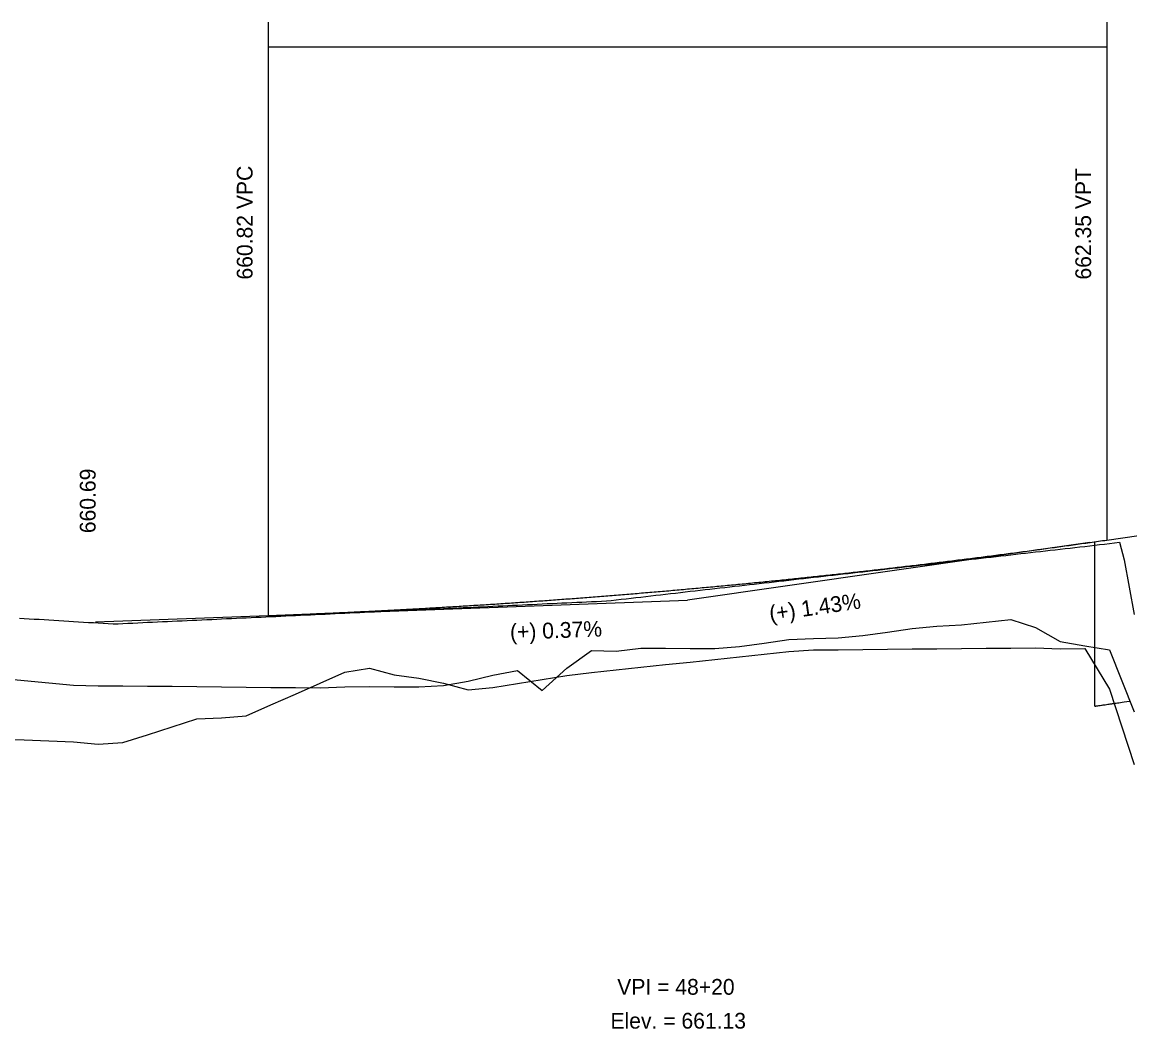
# Model space of a CAD drawing. Extents: x 1733584 to 1737559, y 1214897 to 1219897.
# Drawn here: x 1735164.9 to 1735389.4, y 1217921.2 to 1218125.3 of the extents above; entities that cross this region are included whole.
import ezdxf

# ---------------------------------------------------------------- set-up
doc = ezdxf.new("R2010")
doc.units = 0
for name, color, linetype in [('RD_DDB_GradeTX', 7, 'Continuous'), ('RD_DDB_Profile_EX', 7, 'Continuous'), ('RD_DDB_Profile_Lbl', 7, 'Continuous'), ('RD_DDB_Profile_PR', 7, 'Continuous'), ('RD_DDB_StripGrade', 7, 'Continuous'), ('RD_DDB_VCLbl', 7, 'Continuous'), ('RD_PD_Bridge', 7, 'Continuous'), ('RD_Sketch1', 7, 'Continuous'), ('RD_Sketch2', 7, 'Continuous')]:
    doc.layers.add(name, color=color, linetype=linetype)

msp = doc.modelspace()

# ---------------------------------------------------------------- linework, layer by layer
at = {"layer": 'RD_DDB_GradeTX'}
for p in [(1735381.34, 1218019.81), (1735217.43, 1218005.08)]:
    msp.add_line(p, (1735299.77, 1218008.11), dxfattribs=at)
at = {"layer": 'RD_DDB_Profile_EX'}
for points in [[(1735280.31, 1218007.82), (1735281.31, 1218007.86), (1735282.31, 1218007.91), (1735283.31, 1218007.96), (1735284.31, 1218008.07), (1735285.31, 1218008.18), (1735286.31, 1218008.29), (1735287.31, 1218008.41), (1735288.31, 1218008.52), (1735289.31, 1218008.64), (1735290.31, 1218008.75), (1735291.31, 1218008.87), (1735292.31, 1218008.98), (1735293.31, 1218009.1), (1735294.31, 1218009.21), (1735295.31, 1218009.33), (1735296.31, 1218009.44), (1735297.31, 1218009.55), (1735298.31, 1218009.67), (1735299.31, 1218009.78), (1735300.31, 1218009.9), (1735301.31, 1218010.01), (1735302.31, 1218010.13), (1735303.31, 1218010.24), (1735304.31, 1218010.36), (1735305.31, 1218010.47), (1735306.31, 1218010.58), (1735307.31, 1218010.7), (1735308.31, 1218010.81), (1735309.31, 1218010.92), (1735310.31, 1218011.04), (1735311.31, 1218011.15), (1735312.31, 1218011.26), (1735313.31, 1218011.38), (1735314.31, 1218011.49), (1735315.31, 1218011.6), (1735316.31, 1218011.72), (1735317.31, 1218011.83), (1735318.31, 1218011.95), (1735319.31, 1218012.06), (1735320.31, 1218012.17), (1735321.31, 1218012.29), (1735322.31, 1218012.4), (1735323.31, 1218012.51), (1735324.31, 1218012.63), (1735325.31, 1218012.74), (1735326.31, 1218012.85), (1735327.31, 1218012.97), (1735328.31, 1218013.08), (1735329.31, 1218013.19), (1735330.31, 1218013.31), (1735331.31, 1218013.42), (1735332.31, 1218013.54), (1735333.31, 1218013.65), (1735334.31, 1218013.77), (1735335.31, 1218013.88), (1735336.31, 1218014), (1735337.31, 1218014.11), (1735338.31, 1218014.22), (1735339.31, 1218014.34), (1735340.31, 1218014.45), (1735341.31, 1218014.57), (1735342.31, 1218014.68), (1735343.31, 1218014.79), (1735344.31, 1218014.91), (1735345.31, 1218015.02), (1735346.31, 1218015.13), (1735347.31, 1218015.25), (1735348.31, 1218015.36), (1735349.31, 1218015.48), (1735350.31, 1218015.59), (1735351.31, 1218015.7), (1735352.31, 1218015.82), (1735353.31, 1218015.93), (1735354.31, 1218016.04), (1735355.31, 1218016.16), (1735356.31, 1218016.27), (1735357.31, 1218016.39), (1735358.31, 1218016.51), (1735359.31, 1218016.62), (1735360.31, 1218016.74), (1735361.31, 1218016.85), (1735362.31, 1218016.97), (1735363.31, 1218017.08), (1735364.31, 1218017.19), (1735365.31, 1218017.31), (1735366.31, 1218017.42), (1735367.31, 1218017.54), (1735368.31, 1218017.65), (1735369.31, 1218017.76), (1735370.31, 1218017.88), (1735371.31, 1218017.99), (1735372.31, 1218018.11), (1735373.31, 1218018.22), (1735374.31, 1218018.33), (1735375.31, 1218018.45), (1735376.31, 1218018.56), (1735377.31, 1218018.68), (1735378.31, 1218018.79), (1735379.31, 1218018.9), (1735380.31, 1218019.02)], [(1735380.31, 1218019.02), (1735381.31, 1218019.13), (1735382.31, 1218019.25), (1735383.31, 1218019.38), (1735384.31, 1218019.49), (1735385.31, 1218019.61), (1735386.31, 1218019.72), (1735387.31, 1218019.84), (1735388.31, 1218016.3), (1735389.31, 1218010.76), (1735390.31, 1218005.23)], [(1735180.31, 1218003.49), (1735181.31, 1218003.43), (1735182.31, 1218003.37), (1735183.31, 1218003.3), (1735184.31, 1218003.33), (1735185.31, 1218003.38), (1735186.31, 1218003.43), (1735187.31, 1218003.47), (1735188.31, 1218003.52), (1735189.31, 1218003.57), (1735190.31, 1218003.62), (1735191.31, 1218003.66), (1735192.31, 1218003.71), (1735193.31, 1218003.76), (1735194.31, 1218003.8), (1735195.31, 1218003.85), (1735196.31, 1218003.9), (1735197.31, 1218003.94), (1735198.31, 1218003.99), (1735199.31, 1218004.04), (1735200.31, 1218004.08), (1735201.31, 1218004.13), (1735202.31, 1218004.18), (1735203.31, 1218004.22), (1735204.31, 1218004.27), (1735205.31, 1218004.32), (1735206.31, 1218004.36), (1735207.31, 1218004.41), (1735208.31, 1218004.46), (1735209.31, 1218004.5), (1735210.31, 1218004.55), (1735211.31, 1218004.6), (1735212.31, 1218004.64), (1735213.31, 1218004.69), (1735214.31, 1218004.74), (1735215.31, 1218004.78), (1735216.31, 1218004.83), (1735217.31, 1218004.88), (1735218.31, 1218004.92), (1735219.31, 1218004.97), (1735220.31, 1218005.02), (1735221.31, 1218005.06), (1735222.31, 1218005.11), (1735223.31, 1218005.16), (1735224.31, 1218005.2), (1735225.31, 1218005.25), (1735226.31, 1218005.3), (1735227.31, 1218005.34), (1735228.31, 1218005.39), (1735229.31, 1218005.44), (1735230.31, 1218005.48), (1735231.31, 1218005.53), (1735232.31, 1218005.58), (1735233.31, 1218005.62), (1735234.31, 1218005.67), (1735235.31, 1218005.72), (1735236.31, 1218005.76), (1735237.31, 1218005.81), (1735238.31, 1218005.86), (1735239.31, 1218005.9), (1735240.31, 1218005.95), (1735241.31, 1218006), (1735242.31, 1218006.04), (1735243.31, 1218006.09), (1735244.31, 1218006.14), (1735245.31, 1218006.18), (1735246.31, 1218006.23), (1735247.31, 1218006.28), (1735248.31, 1218006.32), (1735249.31, 1218006.37), (1735250.31, 1218006.42), (1735251.31, 1218006.46), (1735252.31, 1218006.51), (1735253.31, 1218006.56), (1735254.31, 1218006.6), (1735255.31, 1218006.65), (1735256.31, 1218006.7), (1735257.31, 1218006.74), (1735258.31, 1218006.79), (1735259.31, 1218006.84), (1735260.31, 1218006.88), (1735261.31, 1218006.93), (1735262.31, 1218006.98), (1735263.31, 1218007.02), (1735264.31, 1218007.07), (1735265.31, 1218007.12), (1735266.31, 1218007.16), (1735267.31, 1218007.21), (1735268.31, 1218007.26), (1735269.31, 1218007.3), (1735270.31, 1218007.35), (1735271.31, 1218007.4), (1735272.31, 1218007.44), (1735273.31, 1218007.49), (1735274.31, 1218007.54), (1735275.31, 1218007.58), (1735276.31, 1218007.63), (1735277.31, 1218007.68), (1735278.31, 1218007.72), (1735279.31, 1218007.77), (1735280.31, 1218007.82)], [(1735164.31, 1218004.47), (1735165.31, 1218004.41), (1735166.31, 1218004.35), (1735167.31, 1218004.29), (1735168.31, 1218004.23), (1735169.31, 1218004.17), (1735170.31, 1218004.11), (1735171.31, 1218004.04), (1735172.31, 1218003.98), (1735173.31, 1218003.92), (1735174.31, 1218003.86), (1735175.31, 1218003.8), (1735176.31, 1218003.74), (1735177.31, 1218003.67), (1735178.31, 1218003.61), (1735179.31, 1218003.55), (1735180.31, 1218003.49)]]:
    msp.add_lwpolyline(points, dxfattribs=at)
at = {"layer": 'RD_DDB_Profile_PR'}
for p, q in [((1735384.77, 1218020.3), (1735504.77, 1218037.5)), ((1735179.77, 1218003.69), (1735214.77, 1218004.98))]:
    msp.add_line(p, q, dxfattribs=at)
msp.add_spline([(1735214.77, 1218004.98), (1735218.17, 1218005.11), (1735221.57, 1218005.25), (1735224.97, 1218005.39), (1735228.37, 1218005.54), (1735231.77, 1218005.7), (1735235.17, 1218005.86), (1735238.57, 1218006.04), (1735241.97, 1218006.22), (1735245.37, 1218006.4), (1735248.77, 1218006.6), (1735252.17, 1218006.8), (1735255.57, 1218007.01), (1735258.97, 1218007.22), (1735262.37, 1218007.44), (1735265.77, 1218007.67), (1735269.17, 1218007.91), (1735272.57, 1218008.16), (1735275.97, 1218008.41), (1735279.37, 1218008.67), (1735282.77, 1218008.93), (1735286.17, 1218009.21), (1735289.57, 1218009.49), (1735292.97, 1218009.78), (1735296.37, 1218010.07), (1735299.77, 1218010.38), (1735303.17, 1218010.69), (1735306.57, 1218011), (1735309.97, 1218011.33), (1735313.37, 1218011.66), (1735316.77, 1218012), (1735320.17, 1218012.34), (1735323.57, 1218012.7), (1735326.97, 1218013.06), (1735330.37, 1218013.43), (1735333.77, 1218013.8), (1735337.17, 1218014.18), (1735340.57, 1218014.57), (1735343.97, 1218014.97), (1735347.37, 1218015.37), (1735350.77, 1218015.79), (1735354.17, 1218016.2), (1735357.57, 1218016.63), (1735360.97, 1218017.06), (1735364.37, 1218017.5), (1735367.77, 1218017.95), (1735371.17, 1218018.41), (1735374.57, 1218018.87), (1735377.97, 1218019.34), (1735381.37, 1218019.81), (1735384.77, 1218020.3)], degree=3, dxfattribs=at)
at = {"layer": 'RD_DDB_VCLbl'}
for p, q in [((1735214.77, 1218125.3), (1735214.77, 1218004.98)), ((1735384.77, 1218125.3), (1735384.77, 1218020.3)), ((1735214.77, 1218120.3), (1735384.77, 1218120.3))]:
    msp.add_line(p, q, dxfattribs=at)
at = {"layer": 'RD_PD_Bridge'}
msp.add_line((1735382.32, 1217986.63), (1735382.32, 1218019.95), dxfattribs=at)
msp.add_open_spline([(1735382.32, 1217986.63), (1735382.34, 1217986.63), (1735382.39, 1217986.63), (1735382.45, 1217986.64), (1735382.49, 1217986.65), (1735382.51, 1217986.65), (1735382.52, 1217986.65), (1735382.53, 1217986.65), (1735382.6, 1217986.66), (1735382.66, 1217986.67), (1735383.16, 1217986.74), (1735383.6, 1217986.8), (1735384.51, 1217986.93), (1735384.96, 1217986.99), (1735385.54, 1217987.08), (1735385.72, 1217987.1), (1735385.91, 1217987.13), (1735385.99, 1217987.14), (1735386.01, 1217987.14), (1735386.02, 1217987.14), (1735386.02, 1217987.14), (1735386.02, 1217987.14), (1735386.03, 1217987.14), (1735386.06, 1217987.15), (1735386.31, 1217987.18), (1735387.44, 1217987.35), (1735388.54, 1217987.5), (1735389.42, 1217987.63)], degree=3, dxfattribs=at)
at = {"layer": 'RD_Sketch1'}
for points in [[(1735160.31, 1217979.94), (1735165.31, 1217979.77), (1735170.31, 1217979.6), (1735175.31, 1217979.41), (1735180.31, 1217978.94), (1735185.31, 1217979.22), (1735190.31, 1217980.83), (1735195.31, 1217982.44), (1735200.31, 1217984.05), (1735205.31, 1217984.24), (1735210.31, 1217984.65), (1735215.31, 1217986.86), (1735220.31, 1217989.08), (1735225.31, 1217991.29), (1735230.31, 1217993.51), (1735235.31, 1217994.3), (1735240.31, 1217992.98), (1735245.31, 1217992.32), (1735250.31, 1217991.3), (1735255.31, 1217989.94), (1735260.31, 1217990.38), (1735265.31, 1217991.21), (1735270.31, 1217992.04), (1735275.31, 1217992.86), (1735280.31, 1217993.47), (1735285.31, 1217993.99), (1735290.31, 1217994.52), (1735295.31, 1217995.05), (1735300.31, 1217995.57), (1735305.31, 1217996.08), (1735310.31, 1217996.61), (1735315.31, 1217997.14), (1735320.31, 1217997.68), (1735325.31, 1217998.01), (1735330.31, 1217998.06), (1735335.31, 1217998.11), (1735340.31, 1217998.16), (1735345.31, 1217998.21), (1735350.31, 1217998.26), (1735355.31, 1217998.3), (1735360.31, 1217998.35), (1735365.31, 1217998.4), (1735370.31, 1217998.45), (1735375.31, 1217998.24), (1735380.31, 1217998.3)], [(1735380.31, 1217998.3), (1735385.31, 1217990.05), (1735390.31, 1217974.8)]]:
    msp.add_lwpolyline(points, dxfattribs=at)
at = {"layer": 'RD_Sketch2'}
for points in [[(1735160.31, 1217992.29), (1735165.31, 1217991.82), (1735170.31, 1217991.36), (1735175.31, 1217990.89), (1735180.31, 1217990.77), (1735185.31, 1217990.75), (1735190.31, 1217990.7), (1735195.31, 1217990.65), (1735200.31, 1217990.61), (1735205.31, 1217990.53), (1735210.31, 1217990.47), (1735215.31, 1217990.43), (1735220.31, 1217990.38), (1735225.31, 1217990.33), (1735230.31, 1217990.57), (1735235.31, 1217990.62), (1735240.31, 1217990.57), (1735245.31, 1217990.53), (1735250.31, 1217990.78), (1735255.31, 1217991.68), (1735260.31, 1217992.88), (1735265.31, 1217993.82), (1735270.31, 1217989.8), (1735275.31, 1217994.29), (1735280.31, 1217997.93), (1735285.31, 1217997.79), (1735290.31, 1217998.38), (1735295.31, 1217998.36), (1735300.31, 1217998.34), (1735305.31, 1217998.33), (1735310.31, 1217998.69), (1735315.31, 1217999.42), (1735320.31, 1218000.14), (1735325.31, 1218000.31), (1735330.31, 1218000.49), (1735335.31, 1218000.94), (1735340.31, 1218001.64), (1735345.31, 1218002.35), (1735350.31, 1218002.86), (1735355.31, 1218003.14), (1735360.31, 1218003.63), (1735365.31, 1218004.21), (1735370.31, 1218002.56), (1735375.31, 1217999.73), (1735380.31, 1217998.87)], [(1735380.31, 1217998.87), (1735385.31, 1217998.01), (1735390.31, 1217985.5)]]:
    msp.add_lwpolyline(points, dxfattribs=at)

# ---------------------------------------------------------------- texts
at = {"layer": 'RD_DDB_GradeTX'}
for s, rotation, p in [('(+) 1.43%', 8.1594, (1735316.57, 1218003.79)), ('(+) 0.37%', 2.108, (1735263.83, 1218000.06))]:
    msp.add_text(s, height=3.2, rotation=rotation, dxfattribs=at).set_placement(p)
at = {"layer": 'RD_DDB_Profile_Lbl'}
msp.add_text('660.69', height=3.2, rotation=90, dxfattribs=at).set_placement((1735179.77, 1218021.69))
for s, p in [('VPI = 48+20', (1735285.52, 1217928.11)), ('Elev. = 661.13', (1735284.14, 1217921.24))]:
    msp.add_text(s, height=3.2, dxfattribs=at).set_placement(p)
at = {"layer": 'RD_DDB_StripGrade'}
for s, p in [('660.82 VPC', (1735211.59, 1218073.11)), ('662.35 VPT', (1735381.59, 1218073.11))]:
    msp.add_text(s, height=3.2, rotation=90, dxfattribs=at).set_placement(p)

doc.saveas('drawing.dxf')
